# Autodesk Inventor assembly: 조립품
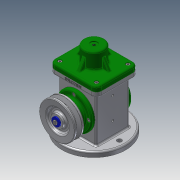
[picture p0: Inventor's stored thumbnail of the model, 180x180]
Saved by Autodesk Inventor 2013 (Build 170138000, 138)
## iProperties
Created: 2018-10
Part Number: 조립품
Document SubType Name: Assembly
Designer: Administrator
Author: Administrator
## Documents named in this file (18)
- C:\Users\Administrator\Desktop\481007V1036\조립품.iam
- C:\Users\Administrator\Desktop\481007V1036\본체.ipt
- C:\Users\Administrator\Desktop\481007V1036\E-링.ipt
- C:\Users\Administrator\Desktop\481007V1036\V-벨트풀리.ipt
- C:\Users\Administrator\Desktop\481007V1036\덮개.ipt
- C:\Users\Administrator\Desktop\481007V1036\뒤커버.ipt
- C:\Users\Administrator\Desktop\481007V1036\링크.ipt
- C:\Users\Administrator\Desktop\481007V1036\베어링 17 x 40 x 12.ipt
- C:\Users\Administrator\Desktop\481007V1036\볼트 M4 x 8.ipt
- C:\Users\Administrator\Desktop\481007V1036\볼트 M4 x 10.ipt
- C:\Users\Administrator\Desktop\481007V1036\슬라이더.ipt
- C:\Users\Administrator\Desktop\481007V1036\앞커버.ipt
- C:\Users\Administrator\Desktop\481007V1036\오일 실 17 30 8.ipt
- C:\Users\Administrator\Desktop\481007V1036\와셔 4x16.ipt
- C:\Users\Administrator\Desktop\481007V1036\클레비스 핀 6 x 22.ipt
- 클레비스 핀 6 x 22.ipt
- C:\Users\Administrator\Desktop\481007V1036\키 4 x 4 x 12.ipt
- C:\Users\Administrator\Desktop\481007V1036\편심축.ipt
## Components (2 placed, 2 different names)
1. E-링:1
2. V-벨트풀리:1
